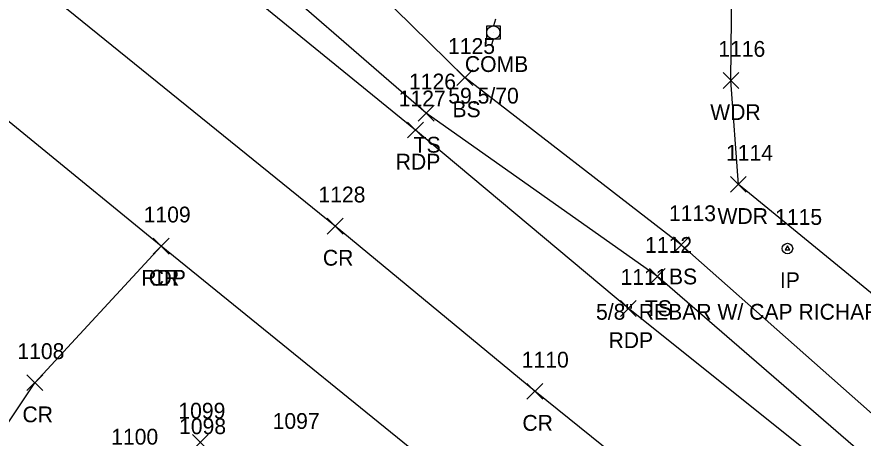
# Model space of a CAD drawing. Extents: x 1537342 to 1542195, y 163002 to 168596.
# Drawn here: x 1541992.5 to 1542099.6, y 163127.1 to 163180.4 of the extents above; entities that cross this region are included whole.
import ezdxf

# ---------------------------------------------------------------- set-up
doc = ezdxf.new("R2010")
doc.units = 0
for name, color, linetype in [('L_A', 7, 'Continuous'), ('L_I', 7, 'Continuous'), ('L_TIC', 7, 'Continuous'), ('LAWA', 7, 'Continuous'), ('LELB', 7, 'Continuous'), ('M_A', 7, 'Continuous'), ('M_C', 7, 'Continuous'), ('M_I', 7, 'Continuous'), ('MPIR', 7, 'Continuous'), ('P_A', 7, 'Continuous'), ('P_I', 7, 'Continuous'), ('P_TIC', 7, 'Continuous'), ('PET', 7, 'Continuous'), ('PRC', 7, 'Continuous'), ('U_A', 7, 'Continuous'), ('U_C', 7, 'Continuous'), ('UP', 7, 'Continuous')]:
    doc.layers.add(name, color=color, linetype=linetype)

msp = doc.modelspace()

# ---------------------------------------------------------------- linework, layer by layer
at = {"layer": 'L_TIC'}
for points in [[(1542048.16, 163171.67), (1542050.16, 163173.67)], [(1542050.16, 163171.67), (1542048.16, 163173.67)], [(1542081.85, 163171.31), (1542083.85, 163173.31)], [(1542083.85, 163171.31), (1542081.85, 163173.31)], [(1542043.28, 163167.18), (1542045.28, 163169.18)], [(1542045.28, 163167.18), (1542043.28, 163169.18)], [(1542082.78, 163158.16), (1542084.78, 163160.16)], [(1542084.78, 163158.16), (1542082.78, 163160.16)], [(1542075.56, 163150.51), (1542077.56, 163152.51)], [(1542077.56, 163150.51), (1542075.56, 163152.51)], [(1542072.54, 163146.5), (1542074.54, 163148.5)], [(1542074.54, 163146.5), (1542072.54, 163148.5)]]:
    msp.add_lwpolyline(points, dxfattribs=at)
at = {"layer": 'LAWA'}
msp.add_lwpolyline([(1542191.37, 163069.26), (1542155.13, 163097.46), (1542123.95, 163126.28), (1542083.78, 163159.16), (1542082.85, 163172.31), (1542083.05, 163192.11), (1542078.54, 163207.24), (1542059.97, 163213.12), (1542055.91, 163226.6), (1542055.2, 163251.61), (1542037.65, 163282.73), (1542029.16, 163294.8)], dxfattribs=at)
at = {"layer": 'LELB'}
for points in [[(1542185.24, 163058.1), (1542149.16, 163088.42), (1542116.16, 163116.47), (1542076.56, 163151.51), (1542049.16, 163172.67), (1542035.85, 163185.79), (1542036.46, 163200.98), (1542035.82, 163228.32), (1542041.31, 163237.99)], [(1542183.12, 163055.05), (1542146.29, 163085.37), (1542113.65, 163112.77), (1542073.54, 163147.5), (1542044.28, 163168.18), (1542019.33, 163189.82), (1542014.69, 163194.08)]]:
    msp.add_lwpolyline(points, dxfattribs=at)
at = {"layer": 'MPIR'}
msp.add_lwpolyline([(1542089.99, 163151.37), (1542089.7, 163150.87), (1542090.28, 163150.87)], close=True, dxfattribs=at)
msp.add_circle((1542089.99, 163151.04), 0.667, dxfattribs=at)
at = {"layer": 'P_TIC'}
for points in [[(1542041.93, 163165.04), (1542043.93, 163167.04)], [(1542043.93, 163165.04), (1542041.93, 163167.04)], [(1542031.76, 163152.88), (1542033.76, 163154.88)], [(1542033.76, 163152.88), (1542031.76, 163154.88)], [(1542009.73, 163150.35), (1542011.73, 163152.35)], [(1542011.73, 163150.35), (1542009.73, 163152.35)], [(1542009.73, 163150.35), (1542011.73, 163152.35)], [(1542011.73, 163150.35), (1542009.73, 163152.35)], [(1542068.86, 163142.45), (1542070.86, 163144.45)], [(1542070.86, 163142.45), (1542068.86, 163144.45)], [(1541993.75, 163133.06), (1541995.75, 163135.06)], [(1541995.75, 163133.06), (1541993.75, 163135.06)], [(1542057.02, 163131.98), (1542059.02, 163133.98)], [(1542059.02, 163131.98), (1542057.02, 163133.98)], [(1542014.69, 163125.52), (1542016.69, 163127.52)], [(1542016.69, 163125.52), (1542014.69, 163127.52)]]:
    msp.add_lwpolyline(points, dxfattribs=at)
at = {"layer": 'PET'}
for points in [[(1542165.56, 163030.05), (1542126.67, 163058.36), (1542096.32, 163082.47), (1542058.61, 163112.54), (1542052.02, 163117.84), (1542010.73, 163151.35), (1541978.73, 163177.48), (1541958.58, 163193.33), (1541928.58, 163217.89), (1541894.65, 163244.61), (1541857.53, 163271.04), (1541839.6, 163283.45), (1541795.58, 163311.16), (1541814.19, 163318.82), (1541832.22, 163326.69)], [(1542182.46, 163052.97), (1542144.74, 163083.14), (1542111.59, 163110.07), (1542069.86, 163143.45), (1542042.93, 163166.04), (1542014.58, 163189.13), (1541996.52, 163203.32), (1541975.27, 163220.84), (1541953.96, 163238.23), (1541914.85, 163268.66), (1541894.39, 163285), (1541874.19, 163298.08), (1541854.83, 163311.47), (1541832.22, 163326.69)]]:
    msp.add_lwpolyline(points, dxfattribs=at)
at = {"layer": 'PRC'}
for points in [[(1542174.18, 163041.84), (1542135.38, 163070.51), (1542102.15, 163097.42), (1542058.02, 163132.98), (1542032.76, 163153.88), (1541982.81, 163194.28), (1541947.35, 163222.57), (1541904.32, 163256.11), (1541874.29, 163278.53), (1541825.99, 163311), (1541814.19, 163318.82)], [(1541969.02, 163092.61), (1541982.1, 163115.12), (1541994.75, 163134.06), (1542010.73, 163151.35)]]:
    msp.add_lwpolyline(points, dxfattribs=at)
at = {"layer": 'UP'}
for p, q in [((1542053.03, 163180.06), (1542052.78, 163179.22)), ((1542051.95, 163177.56), (1542051.95, 163179.22)), ((1542051.95, 163179.22), (1542053.62, 163179.22)), ((1542052.78, 163178.39), (1542052.78, 163178.39)), ((1542053.62, 163179.22), (1542053.62, 163177.56)), ((1542053.62, 163177.56), (1542051.95, 163177.56)), ((1542052.53, 163176.72), (1542052.78, 163177.56))]:
    msp.add_line(p, q, dxfattribs=at)
msp.add_circle((1542052.78, 163178.39), 0.833, dxfattribs=at)

# ---------------------------------------------------------------- texts
at = {"layer": 'L_A'}
for s, p in [('BS', (1542047.6, 163167.67)), ('WDR', (1542080.22, 163167.31)), ('TS', (1542042.69, 163163.18)), ('WDR', (1542081.14, 163154.16)), ('BS', (1542075, 163146.51)), ('TS', (1542071.95, 163142.5))]:
    msp.add_text(s, height=2, dxfattribs=at).set_placement(p)
at = {"layer": 'L_I'}
for s, p in [('1125', (1542047.04, 163175.67)), ('1116', (1542081.24, 163175.31)), ('1126', (1542042.1, 163171.18)), ('1114', (1542082.22, 163162.16)), ('1113', (1542075, 163154.51)), ('1112', (1542071.98, 163150.5)), ('1097', (1542024.84, 163128.22)), ('1098', (1542013, 163127.56))]:
    msp.add_text(s, height=2, dxfattribs=at).set_placement(p)
at = {"layer": 'M_A'}
msp.add_text('IP', height=2, dxfattribs=at).set_placement((1542089.04, 163146.04))
at = {"layer": 'M_C'}
msp.add_text('5/8" REBAR W/ CAP RICHARD H.', height=2, dxfattribs=at).set_placement((1542065.77, 163142.04))
at = {"layer": 'M_I'}
msp.add_text('1115', height=2, dxfattribs=at).set_placement((1542088.43, 163154.04))
at = {"layer": 'P_A'}
for s, p in [('RDP', (1542040.42, 163161.04)), ('CR', (1542031.2, 163148.88)), ('RDP', (1542008.22, 163146.35)), ('CR', (1542009.17, 163146.35)), ('RDP', (1542067.35, 163138.45)), ('CR', (1541993.18, 163129.06)), ('CR', (1542056.45, 163127.98))]:
    msp.add_text(s, height=2, dxfattribs=at).set_placement(p)
at = {"layer": 'P_I'}
for s, p in [('1127', (1542040.8, 163169.04)), ('1128', (1542030.64, 163156.88)), ('1109', (1542008.52, 163154.35)), ('1109', (1542008.52, 163154.35)), ('1111', (1542068.87, 163146.45)), ('1108', (1541992.54, 163137.06)), ('1110', (1542056.37, 163135.98)), ('1099', (1542012.91, 163129.52)), ('1097', (1542024.84, 163128.22)), ('1100', (1542004.41, 163126.23))]:
    msp.add_text(s, height=2, dxfattribs=at).set_placement(p)
at = {"layer": 'U_A'}
msp.add_text('COMB', height=2, dxfattribs=at).set_placement((1542049.17, 163173.39))
at = {"layer": 'U_C'}
msp.add_text('59.5/70', height=2, dxfattribs=at).set_placement((1542047.07, 163169.39))

doc.saveas('drawing.dxf')
